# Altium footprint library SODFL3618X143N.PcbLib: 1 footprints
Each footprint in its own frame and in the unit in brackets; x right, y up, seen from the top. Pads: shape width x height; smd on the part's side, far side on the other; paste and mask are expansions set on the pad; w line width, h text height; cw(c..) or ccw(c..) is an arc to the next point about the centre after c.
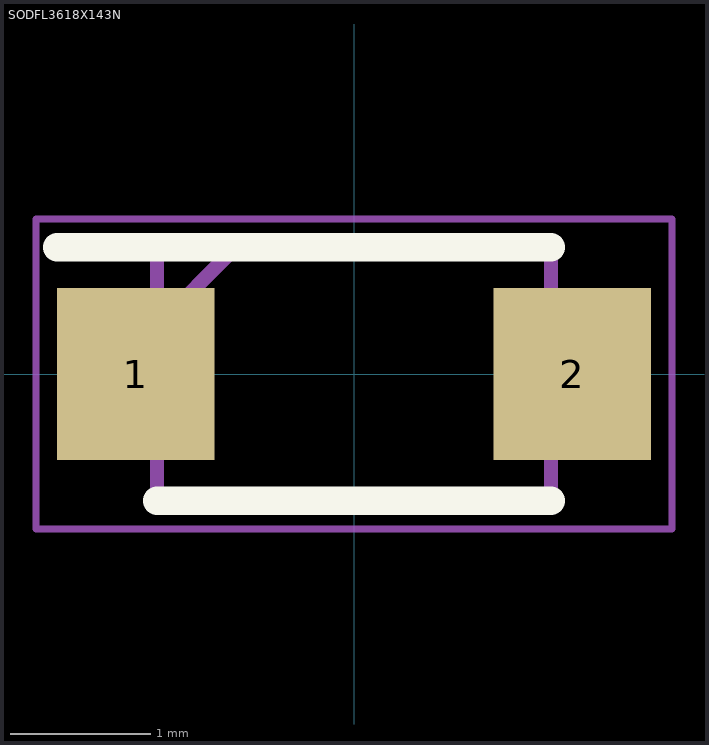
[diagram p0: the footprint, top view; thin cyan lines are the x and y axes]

## SODFL3618X143N [mm]
pads (2):
  rect 1.12x1.22 smd: 1(-1.55,0) 2(1.55,0)
Top Overlay:
  lines w0.2: -2.11,0.9 1.4,0.9 ; -1.4,-0.9 1.4,-0.9
Mechanical 15:
  lines w0.1: -1.4,0.34 -0.84,0.9 ; -1.4,-0.9 1.4,-0.9 1.4,0.9 -1.4,0.9 -1.4,-0.9
Mechanical 20:
  lines w0.05: -2.26,-1.1 2.26,-1.1 2.26,1.1 -2.26,1.1 -2.26,-1.1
